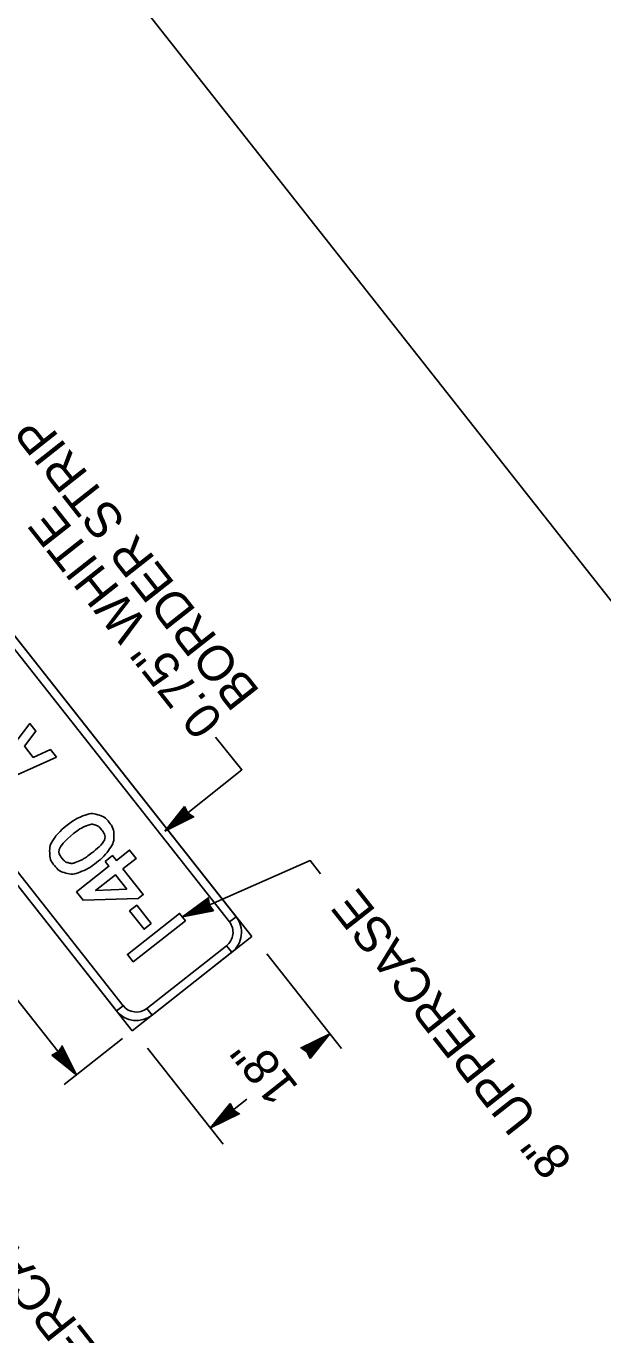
# Model space of a CAD drawing. Extents: x 672438 to 673763, y 1673171 to 1675010.
# Drawn here: x 673378.2 to 673446.4, y 1674719.6 to 1674874.4 of the extents above; entities that cross this region are included whole.
import ezdxf

# ---------------------------------------------------------------- set-up
doc = ezdxf.new("R2010")
doc.units = 0
for name, color, linetype in [('61', 7, 'Continuous'), ('C-ANNO-SYMB', 7, 'Continuous'), ('Level 1', 7, 'Continuous')]:
    doc.layers.add(name, color=color, linetype=linetype)

msp = doc.modelspace()

# ---------------------------------------------------------------- linework, layer by layer
at = {"layer": '61'}
msp.add_lwpolyline([(673588.03, 1674834.72), (673456.99, 1675000.94), (673356.5, 1674921.71), (673487.54, 1674755.49)], close=True, dxfattribs=at)
at = {"layer": 'C-ANNO-SYMB'}
for p, q in [((673360.3, 1674823.26), (673404.88, 1674766.71)), ((673346.17, 1674812.11), (673390.74, 1674755.57)), ((673403.02, 1674769.07), (673402.23, 1674768.45)), ((673390.74, 1674755.57), (673404.88, 1674766.71)), ((673401.9, 1674765.64), (673402.52, 1674764.86)), ((673389.67, 1674758.54), (673388.88, 1674757.93)), ((673393.1, 1674757.43), (673392.48, 1674758.21))]:
    msp.add_line(p, q, dxfattribs=at)
for points in [[(673402.23, 1674768.45), (673361.37, 1674820.28), (673362.16, 1674820.9), (673403.02, 1674769.07), (673402.23, 1674768.45), (673402.23, 1674768.45)], [(673348.81, 1674810.38), (673389.67, 1674758.54), (673388.88, 1674757.93), (673348.02, 1674809.76), (673348.81, 1674810.38), (673348.81, 1674810.38)], [(673392.98, 1674768.26), (673391.27, 1674770.43), (673390.42, 1674769.76), (673392.14, 1674767.59)], [(673397.03, 1674768.59), (673396.34, 1674769.46), (673390.18, 1674764.61), (673390.87, 1674763.74)], [(673392.48, 1674758.21), (673401.9, 1674765.64), (673402.52, 1674764.86), (673393.1, 1674757.43), (673392.48, 1674758.21), (673392.48, 1674758.21)]]:
    msp.add_lwpolyline(points, close=True, dxfattribs=at)
for points in [[(673381.77, 1674787.94), (673381.07, 1674788.84), (673379.04, 1674787.92), (673378, 1674789.25), (673379.35, 1674791.02), (673378.64, 1674791.92), (673373.7, 1674785.51), (673374.39, 1674784.64), (673381.77, 1674787.94)], [(673387.52, 1674775.61), (673388.4, 1674776.3), (673388.86, 1674775.72), (673390.43, 1674776.96), (673391.21, 1674775.97), (673389.64, 1674774.73), (673392.04, 1674771.69), (673391.45, 1674771.22), (673384.93, 1674771.02), (673384.15, 1674772), (673387.98, 1674775.03), (673387.52, 1674775.61)], [(673390.12, 1674772.31), (673388.76, 1674774.04), (673386.41, 1674772.18), (673390.12, 1674772.31)]]:
    msp.add_lwpolyline(points, dxfattribs=at)
for centre, radius, start, end in [((673400.66, 1674767.21), 2, 308.2504, 38.2506), ((673400.66, 1674767.21), 3, 308.2504, 38.2506), ((673391.24, 1674759.78), 3, 218.2508, 308.2504), ((673391.24, 1674759.78), 2, 218.2508, 308.2504)]:
    msp.add_arc(centre, radius, start, end, dxfattribs=at)
for points in [[(673383.03, 1674779.89), (673383.99, 1674780.65), (673385.03, 1674781.04), (673385.83, 1674781.35), (673386.66, 1674781.14), (673387.47, 1674780.92), (673388.01, 1674780.23), (673388.55, 1674779.54), (673388.57, 1674778.7), (673388.59, 1674777.85), (673388.09, 1674777.14), (673387.44, 1674776.22), (673386.51, 1674775.48), (673385.57, 1674774.74), (673384.52, 1674774.33), (673383.71, 1674774.01), (673382.89, 1674774.23), (673382.07, 1674774.45), (673381.53, 1674775.13), (673381, 1674775.81), (673380.98, 1674776.66), (673380.95, 1674777.52), (673381.44, 1674778.22), (673382.08, 1674779.15), (673383.03, 1674779.89)], [(673383.8, 1674778.91), (673381.54, 1674777.13), (673382.51, 1674775.91), (673382.79, 1674775.55), (673383.21, 1674775.44), (673383.63, 1674775.33), (673384.05, 1674775.49), (673384.94, 1674775.83), (673385.74, 1674776.45), (673387.99, 1674778.23), (673387.02, 1674779.47), (673386.74, 1674779.82), (673386.32, 1674779.94), (673385.91, 1674780.05), (673385.49, 1674779.89), (673384.6, 1674779.54), (673383.8, 1674778.91)]]:
    msp.add_open_spline(points, degree=3, dxfattribs=at)
at = {"layer": 'Level 1'}
for p, q in [((673394.6, 1674779.2), (673396.92, 1674782.11)), ((673394.82, 1674779.44), (673396.91, 1674781.96)), ((673396.91, 1674781.96), (673397.25, 1674781.4)), ((673396.92, 1674782.11), (673397.32, 1674781.35)), ((673398.06, 1674780.91), (673394.6, 1674779.2)), ((673397.71, 1674780.89), (673394.86, 1674779.47)), ((673397.87, 1674780.85), (673395.02, 1674779.56)), ((673395.17, 1674779.71), (673396.9, 1674781.79)), ((673395.39, 1674779.81), (673396.95, 1674781.53)), ((673397.59, 1674780.97), (673395.39, 1674779.81)), ((673395.46, 1674779.94), (673396.9, 1674781.66)), ((673397.59, 1674780.97), (673395.46, 1674779.94)), ((673395.9, 1674780.28), (673396.89, 1674781.39)), ((673397.41, 1674781.02), (673395.9, 1674780.28)), ((673396.44, 1674780.64), (673396.19, 1674780.54)), ((673396.28, 1674780.55), (673396.86, 1674781.26)), ((673397.24, 1674781.06), (673396.28, 1674780.55)), ((673396.95, 1674781.4), (673396.44, 1674780.64)), ((673396.62, 1674780.84), (673396.89, 1674781.18)), ((673397.14, 1674781.11), (673396.62, 1674780.84)), ((673396.86, 1674781.26), (673397.14, 1674781.11)), ((673396.89, 1674781.39), (673397.24, 1674781.06)), ((673396.89, 1674781.18), (673396.97, 1674781.12)), ((673396.9, 1674781.79), (673397.04, 1674781.53)), ((673396.9, 1674781.66), (673397.59, 1674780.97)), ((673396.95, 1674781.53), (673397.41, 1674781.02)), ((673397.32, 1674781.13), (673396.95, 1674781.4)), ((673396.97, 1674781.12), (673397.32, 1674781.13)), ((673397.04, 1674781.53), (673397.59, 1674780.97)), ((673397.25, 1674781.4), (673397.92, 1674780.93)), ((673397.32, 1674781.35), (673397.56, 1674781.04)), ((673397.56, 1674781.04), (673397.87, 1674780.85)), ((673397.92, 1674780.93), (673397.7, 1674780.99)), ((673397.7, 1674780.99), (673397.71, 1674780.89)), ((673399.81, 1674771.34), (673396.69, 1674769.07)), ((673399.67, 1674771.19), (673397.2, 1674769.27)), ((673399.69, 1674770.83), (673399.67, 1674771.19)), ((673399.76, 1674771.2), (673399.71, 1674770.97)), ((673399.86, 1674770.38), (673399.76, 1674771.2)), ((673396.69, 1674769.07), (673400.34, 1674769.77)), ((673397, 1674769.15), (673400.2, 1674769.82)), ((673399.63, 1674771.03), (673397.05, 1674769.17)), ((673397.17, 1674769.34), (673397.92, 1674769.85)), ((673397.41, 1674769.33), (673400.05, 1674769.9)), ((673397.92, 1674769.85), (673397.41, 1674769.33)), ((673399.64, 1674770.89), (673397.6, 1674769.48)), ((673397.6, 1674769.48), (673399.84, 1674770.06)), ((673399.64, 1674770.89), (673397.74, 1674769.49)), ((673397.74, 1674769.49), (673399.94, 1674769.96)), ((673398.13, 1674769.69), (673398.52, 1674769.98)), ((673398.61, 1674769.85), (673398.13, 1674769.69)), ((673399.61, 1674770.7), (673398.24, 1674769.71)), ((673398.24, 1674769.71), (673399.68, 1674770.08)), ((673398.82, 1674770.03), (673398.61, 1674769.85)), ((673399.56, 1674770.54), (673398.66, 1674769.93)), ((673398.66, 1674769.93), (673399.56, 1674770.1)), ((673399.72, 1674770.12), (673398.82, 1674770.03)), ((673399.56, 1674770.42), (673399.08, 1674770.09)), ((673399.08, 1674770.09), (673399.5, 1674770.17)), ((673399.48, 1674770.27), (673399.66, 1674770.58)), ((673399.5, 1674770.17), (673399.48, 1674770.27)), ((673399.68, 1674770.08), (673399.56, 1674770.54)), ((673399.56, 1674770.1), (673399.56, 1674770.42)), ((673399.84, 1674770.06), (673399.61, 1674770.7)), ((673399.71, 1674770.97), (673399.63, 1674771.03)), ((673399.89, 1674770.14), (673399.64, 1674770.89)), ((673399.94, 1674769.96), (673399.64, 1674770.89)), ((673399.66, 1674770.58), (673399.72, 1674770.12)), ((673399.85, 1674770.47), (673399.69, 1674770.83)), ((673400.34, 1674769.77), (673399.85, 1674770.47)), ((673400.2, 1674769.82), (673399.86, 1674770.38)), ((673400.05, 1674769.9), (673399.89, 1674770.14)), ((673384.13, 1674750.35), (673369.51, 1674768.89)), ((673397.2, 1674769.27), (673397, 1674769.15)), ((673397.05, 1674769.17), (673397.17, 1674769.34)), ((673406.66, 1674764.68), (673415.49, 1674753.48)), ((673389.59, 1674754.66), (673382.68, 1674749.22)), ((673410.66, 1674753.51), (673414.13, 1674755.21)), ((673410.86, 1674753.56), (673413.7, 1674754.85)), ((673411.02, 1674753.52), (673413.87, 1674754.94)), ((673411.14, 1674753.45), (673413.34, 1674754.6)), ((673411.14, 1674753.45), (673413.27, 1674754.48)), ((673411.32, 1674753.39), (673412.83, 1674754.14)), ((673413.34, 1674754.6), (673411.78, 1674752.89)), ((673414.13, 1674755.21), (673411.8, 1674752.3)), ((673413.91, 1674754.98), (673411.82, 1674752.45)), ((673413.56, 1674754.7), (673411.82, 1674752.62)), ((673413.27, 1674754.48), (673411.82, 1674752.75)), ((673412.83, 1674754.14), (673411.84, 1674753.03)), ((673412.9, 1674754.22), (673412.46, 1674754.02)), ((673412.54, 1674753.88), (673412.9, 1674754.22)), ((673413.66, 1674754.91), (673412.86, 1674754.49)), ((673412.86, 1674754.49), (673413.56, 1674754.7)), ((673413.87, 1674754.94), (673413.66, 1674754.91)), ((673413.7, 1674754.85), (673413.91, 1674754.98)), ((673381.22, 1674752.68), (673381.98, 1674753.07)), ((673384.13, 1674750.35), (673381.22, 1674752.68)), ((673381.37, 1674752.66), (673381.93, 1674753)), ((673383.89, 1674750.57), (673381.37, 1674752.66)), ((673381.53, 1674752.65), (673381.79, 1674752.79)), ((673383.61, 1674750.92), (673381.53, 1674752.65)), ((673381.66, 1674752.66), (673382.36, 1674753.34)), ((673383.39, 1674751.21), (673381.66, 1674752.66)), ((673381.79, 1674752.79), (673382.36, 1674753.34)), ((673381.8, 1674752.7), (673382.3, 1674753.16)), ((673383.51, 1674751.14), (673381.8, 1674752.7)), ((673381.93, 1674753), (673382.4, 1674753.67)), ((673382.2, 1674753.08), (673381.93, 1674752.7)), ((673381.93, 1674752.7), (673382.69, 1674752.19)), ((673381.94, 1674752.64), (673382.27, 1674752.99)), ((673383.05, 1674751.65), (673381.94, 1674752.64)), ((673381.98, 1674753.07), (673382.29, 1674753.31)), ((673382.07, 1674752.61), (673382.22, 1674752.89)), ((673382.78, 1674752.03), (673382.07, 1674752.61)), ((673382.15, 1674752.64), (673382.21, 1674752.72)), ((673382.49, 1674752.37), (673382.15, 1674752.64)), ((673382.21, 1674752.72), (673382.2, 1674753.08)), ((673382.22, 1674752.89), (673382.49, 1674752.37)), ((673382.27, 1674752.99), (673382.78, 1674752.03)), ((673382.29, 1674753.31), (673382.47, 1674753.62)), ((673382.3, 1674753.16), (673383.05, 1674751.65)), ((673382.4, 1674753.67), (673382.34, 1674753.45)), ((673382.34, 1674753.45), (673382.44, 1674753.46)), ((673382.36, 1674753.34), (673383.39, 1674751.21)), ((673382.36, 1674753.34), (673383.51, 1674751.14)), ((673382.42, 1674753.82), (673384.13, 1674750.35)), ((673382.44, 1674753.46), (673383.86, 1674750.61)), ((673382.47, 1674753.62), (673383.77, 1674750.77)), ((673392.53, 1674753.53), (673401.48, 1674742.17)), ((673411.48, 1674753.02), (673410.81, 1674753.49)), ((673410.81, 1674753.49), (673411.03, 1674753.43)), ((673411.17, 1674753.37), (673410.86, 1674753.56)), ((673411.03, 1674753.43), (673411.02, 1674753.52)), ((673411.69, 1674752.88), (673411.14, 1674753.45)), ((673411.82, 1674752.75), (673411.14, 1674753.45)), ((673411.41, 1674753.06), (673411.17, 1674753.37)), ((673411.78, 1674752.89), (673411.32, 1674753.39)), ((673411.76, 1674753.3), (673411.4, 1674753.29)), ((673411.4, 1674753.29), (673411.78, 1674753.02)), ((673411.8, 1674752.3), (673411.41, 1674753.06)), ((673411.48, 1674753.35), (673412.44, 1674753.87)), ((673411.84, 1674753.03), (673411.48, 1674753.35)), ((673411.82, 1674752.45), (673411.48, 1674753.02)), ((673411.59, 1674753.3), (673412.11, 1674753.57)), ((673411.87, 1674753.16), (673411.59, 1674753.3)), ((673411.82, 1674752.62), (673411.69, 1674752.88)), ((673411.84, 1674753.23), (673411.76, 1674753.3)), ((673411.78, 1674753.02), (673412.28, 1674753.78)), ((673412.11, 1674753.57), (673411.84, 1674753.23)), ((673412.44, 1674753.87), (673411.87, 1674753.16)), ((673412.28, 1674753.78), (673412.54, 1674753.88)), ((673382.69, 1674752.19), (673382.79, 1674751.94)), ((673382.79, 1674751.94), (673383.14, 1674751.58)), ((673383.14, 1674751.58), (673382.93, 1674752.01)), ((673383.83, 1674750.82), (673383.4, 1674751.62)), ((673383.4, 1674751.62), (673383.61, 1674750.92)), ((673383.77, 1674750.77), (673383.89, 1674750.57)), ((673383.86, 1674750.61), (673383.83, 1674750.82)), ((673399.99, 1674744.07), (673404.31, 1674747.48)), ((673399.99, 1674744.07), (673402.31, 1674746.98)), ((673400.21, 1674744.3), (673402.29, 1674746.83)), ((673400.56, 1674744.58), (673402.29, 1674746.66)), ((673400.78, 1674744.68), (673402.33, 1674746.39)), ((673400.85, 1674744.8), (673402.29, 1674746.53)), ((673402.29, 1674746.83), (673402.63, 1674746.26)), ((673402.29, 1674746.66), (673402.43, 1674746.4)), ((673402.29, 1674746.53), (673402.97, 1674745.83)), ((673402.31, 1674746.98), (673402.7, 1674746.22)), ((673402.33, 1674746.39), (673402.79, 1674745.89)), ((673402.43, 1674746.4), (673402.97, 1674745.83)), ((673403.45, 1674745.77), (673399.99, 1674744.07)), ((673403.09, 1674745.76), (673400.25, 1674744.34)), ((673403.26, 1674745.72), (673400.41, 1674744.43)), ((673400.46, 1674744.37), (673401.26, 1674744.79)), ((673401.26, 1674744.79), (673400.56, 1674744.58)), ((673402.97, 1674745.83), (673400.78, 1674744.68)), ((673402.97, 1674745.83), (673400.85, 1674744.8)), ((673401.58, 1674745.4), (673401.22, 1674745.06)), ((673401.22, 1674745.06), (673401.65, 1674745.26)), ((673401.28, 1674745.14), (673402.28, 1674746.25)), ((673402.79, 1674745.89), (673401.28, 1674745.14)), ((673401.83, 1674745.5), (673401.58, 1674745.4)), ((673401.67, 1674745.41), (673402.24, 1674746.12)), ((673402.63, 1674745.93), (673401.67, 1674745.41)), ((673402.34, 1674746.26), (673401.83, 1674745.5)), ((673402.01, 1674745.71), (673402.27, 1674746.05)), ((673402.52, 1674745.98), (673402.01, 1674745.71)), ((673402.24, 1674746.12), (673402.52, 1674745.98)), ((673402.27, 1674746.05), (673402.35, 1674745.98)), ((673402.28, 1674746.25), (673402.63, 1674745.93)), ((673402.71, 1674745.99), (673402.34, 1674746.26)), ((673402.35, 1674745.98), (673402.71, 1674745.99)), ((673402.63, 1674746.26), (673403.3, 1674745.79)), ((673402.7, 1674746.22), (673402.94, 1674745.91)), ((673402.94, 1674745.91), (673403.26, 1674745.72)), ((673403.3, 1674745.79), (673403.09, 1674745.85)), ((673403.09, 1674745.85), (673403.09, 1674745.76)), ((673400.41, 1674744.43), (673400.21, 1674744.3)), ((673400.25, 1674744.34), (673400.46, 1674744.37))]:
    msp.add_line(p, q, dxfattribs=at)
for points in [[(673394.6, 1674779.2), (673403.72, 1674786.46), (673400.58, 1674790.32)], [(673396.69, 1674769.07), (673411.8, 1674775.7), (673413.02, 1674774.15)]]:
    msp.add_lwpolyline(points, dxfattribs=at)

# ---------------------------------------------------------------- texts
for s, p in [('BORDER STRIP', (673405.94, 1674795.72)), ('0.75" WHITE ', (673401.65, 1674792.33)), ('8" UPPERCASE', (673442.94, 1674740.21)), ('18"', (673410.53, 1674748.91)), ('8" UPPERCASE', (673398.01, 1674703.79))]:
    msp.add_text(s, height=4.2, rotation=128.2505, dxfattribs=at).set_placement(p)

doc.saveas('drawing.dxf')
